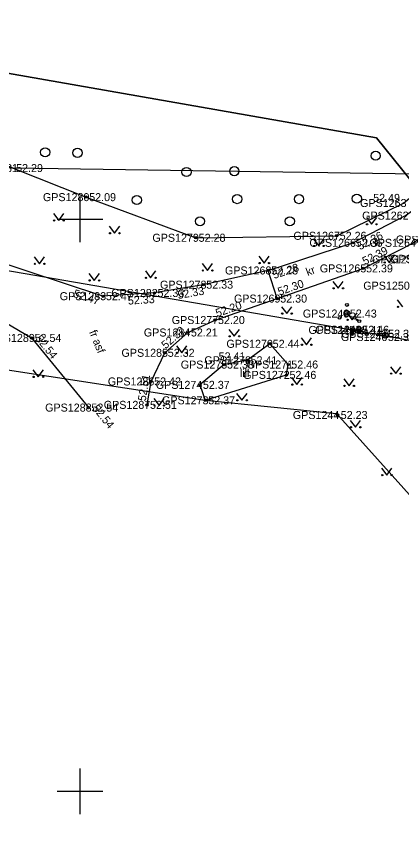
# Model space of a CAD drawing. Extents: x 551623 to 559850, y 6561220 to 6567135.
# Drawn here: x 555194.4 to 555228.1, y 6565096.7 to 6565167.7 of the extents above; entities that cross this region are included whole.
import ezdxf

# ---------------------------------------------------------------- set-up
doc = ezdxf.new("R2010")
doc.units = 0
for name, color, linetype in [('HALJASTUS', 7, 'Continuous'), ('KORGUS-EH2000', 7, 'Continuous'), ('KPOHULIIN', 7, 'Continuous'), ('MOOTKORG-EH2000', 7, 'Continuous'), ('MOOTMPUNKT', 7, 'Continuous'), ('MOOTNR', 7, 'Continuous'), ('MOOTPIIR', 7, 'Continuous'), ('PIIR', 7, 'Continuous'), ('POST', 7, 'Continuous'), ('PUU', 7, 'Continuous'), ('TEE', 7, 'Continuous'), ('VORK', 7, 'Continuous')]:
    doc.layers.add(name, color=color, linetype=linetype)

msp = doc.modelspace()

# ---------------------------------------------------------------- linework, layer by layer
at = {"layer": 'HALJASTUS'}
for p, q in [((555197.689, 6565150.508), (555198.153, 6565149.901)), ((555198.153, 6565149.901), (555198.598, 6565150.508)), ((555225.009, 6565150.165), (555225.472, 6565149.558)), ((555225.472, 6565149.558), (555225.918, 6565150.165)), ((555202.562, 6565149.385), (555203.025, 6565148.778)), ((555203.025, 6565148.778), (555203.471, 6565149.385)), ((555220.397, 6565148.274), (555220.861, 6565147.667)), ((555220.861, 6565147.667), (555221.306, 6565148.274)), ((555196, 6565146.709), (555196.464, 6565146.102)), ((555196.464, 6565146.102), (555196.909, 6565146.709)), ((555215.626, 6565146.78), (555216.089, 6565146.173)), ((555216.089, 6565146.173), (555216.535, 6565146.78)), ((555226.548, 6565146.826), (555227.012, 6565146.219)), ((555227.012, 6565146.219), (555227.457, 6565146.826)), ((555210.669, 6565146.129), (555211.133, 6565145.522)), ((555211.133, 6565145.522), (555211.578, 6565146.129)), ((555200.786, 6565145.261), (555201.25, 6565144.654)), ((555201.25, 6565144.654), (555201.695, 6565145.261)), ((555205.711, 6565145.488), (555206.174, 6565144.881)), ((555206.174, 6565144.881), (555206.62, 6565145.488)), ((555222.085, 6565144.574), (555222.548, 6565143.967)), ((555222.548, 6565143.967), (555222.994, 6565144.574)), ((555227.704, 6565142.95), (555228.168, 6565142.343)), ((555217.602, 6565142.361), (555218.065, 6565141.754)), ((555218.065, 6565141.754), (555218.511, 6565142.361)), ((555223.308, 6565141.818), (555223.771, 6565141.211)), ((555223.771, 6565141.211), (555224.217, 6565141.818)), ((555213.012, 6565140.378), (555213.475, 6565139.771)), ((555213.475, 6565139.771), (555213.921, 6565140.378)), ((555219.32, 6565139.641), (555219.783, 6565139.034)), ((555219.783, 6565139.034), (555220.229, 6565139.641)), ((555208.419, 6565138.924), (555208.883, 6565138.317)), ((555208.883, 6565138.317), (555209.328, 6565138.924)), ((555195.895, 6565136.829), (555196.358, 6565136.222)), ((555196.358, 6565136.222), (555196.804, 6565136.829)), ((555227.113, 6565137.114), (555227.577, 6565136.508)), ((555227.577, 6565136.508), (555228.022, 6565137.114)), ((555218.486, 6565136.16), (555218.949, 6565135.553)), ((555218.949, 6565135.553), (555219.395, 6565136.16)), ((555223.035, 6565136.044), (555223.499, 6565135.437)), ((555223.499, 6565135.437), (555223.944, 6565136.044)), ((555213.68, 6565134.781), (555214.143, 6565134.175)), ((555214.143, 6565134.175), (555214.589, 6565134.781)), ((555206.451, 6565134.328), (555206.914, 6565133.721)), ((555206.914, 6565133.721), (555207.36, 6565134.328)), ((555223.598, 6565132.426), (555224.062, 6565131.819)), ((555224.062, 6565131.819), (555224.507, 6565132.426)), ((555226.335, 6565128.241), (555226.798, 6565127.634)), ((555226.798, 6565127.634), (555227.244, 6565128.241))]:
    msp.add_line(p, q, dxfattribs=at)
for points in [[(555170.849, 6565163.433), (555170.802, 6565162.422), (555180.588, 6565157.338), (555194.166, 6565154.476), (555200.547, 6565151.934), (555210.105, 6565148.383), (555222.421, 6565148.556), (555228.239, 6565151.421), (555231.104, 6565153.786)], [(555216.57, 6565139.116), (555214.639, 6565137.676), (555212.583, 6565137.299), (555210.474, 6565135.526), (555210.946, 6565134.177), (555218.038, 6565136.397), (555218.195, 6565137.306), (555216.57, 6565139.116)]]:
    msp.add_lwpolyline(points, dxfattribs=at)
for centre, radius in [((555196.963, 6565155.852), 0.4), ((555199.786, 6565155.81), 0.4), ((555225.824, 6565155.557), 0.4), ((555209.308, 6565154.124), 0.4), ((555213.479, 6565154.208), 0.4), ((555213.732, 6565151.763), 0.4), ((555219.125, 6565151.763), 0.4), ((555224.181, 6565151.805), 0.4), ((555204.968, 6565151.678), 0.4), ((555210.488, 6565149.823), 0.4), ((555218.325, 6565149.823), 0.4), ((555197.752, 6565149.901), 0.055), ((555198.581, 6565149.901), 0.055), ((555225.071, 6565149.558), 0.055), ((555225.9, 6565149.558), 0.055), ((555202.624, 6565148.778), 0.055), ((555203.453, 6565148.778), 0.055), ((555220.46, 6565147.667), 0.055), ((555221.289, 6565147.667), 0.055), ((555196.063, 6565146.102), 0.055), ((555196.892, 6565146.102), 0.055), ((555215.688, 6565146.173), 0.055), ((555216.517, 6565146.173), 0.055), ((555226.611, 6565146.219), 0.055), ((555227.44, 6565146.219), 0.055), ((555210.732, 6565145.522), 0.055), ((555211.56, 6565145.522), 0.055), ((555200.848, 6565144.654), 0.055), ((555201.677, 6565144.654), 0.055), ((555205.773, 6565144.881), 0.055), ((555206.602, 6565144.881), 0.055), ((555222.147, 6565143.967), 0.055), ((555222.976, 6565143.967), 0.055), ((555227.767, 6565142.343), 0.055), ((555217.664, 6565141.754), 0.055), ((555218.493, 6565141.754), 0.055), ((555223.37, 6565141.211), 0.055), ((555224.199, 6565141.211), 0.055), ((555213.074, 6565139.771), 0.055), ((555213.903, 6565139.771), 0.055), ((555219.382, 6565139.034), 0.055), ((555220.211, 6565139.034), 0.055), ((555208.482, 6565138.317), 0.055), ((555209.311, 6565138.317), 0.055), ((555227.175, 6565136.508), 0.055), ((555228.004, 6565136.508), 0.055), ((555195.957, 6565136.222), 0.055), ((555196.786, 6565136.222), 0.055), ((555218.548, 6565135.553), 0.055), ((555219.377, 6565135.553), 0.055), ((555223.098, 6565135.437), 0.055), ((555223.927, 6565135.437), 0.055), ((555206.513, 6565133.721), 0.055), ((555207.342, 6565133.721), 0.055), ((555213.742, 6565134.175), 0.055), ((555214.571, 6565134.175), 0.055), ((555223.661, 6565131.819), 0.055), ((555224.49, 6565131.819), 0.055), ((555226.397, 6565127.634), 0.055), ((555227.226, 6565127.634), 0.055)]:
    msp.add_circle(centre, radius, dxfattribs=at)
at = {"layer": 'KORGUS-EH2000'}
for centre in [(555200.547, 6565151.934), (555222.421, 6565148.556), (555210.105, 6565148.383), (555223.819, 6565147.942), (555224.725, 6565145.706), (555216.442, 6565145.526), (555210.771, 6565144.283), (555206.511, 6565143.557), (555202.006, 6565143.277), (555217.229, 6565143.067), (555223.313, 6565141.76), (555211.794, 6565141.192), (555195.778, 6565139.63), (555207.407, 6565138.329), (555214.639, 6565137.676), (555218.038, 6565136.397), (555205.86, 6565133.779), (555210.946, 6565134.177), (555200.739, 6565133.541), (555222.511, 6565132.893)]:
    msp.add_circle(centre, 0.1, dxfattribs=at)
at = {"layer": 'KPOHULIIN'}
msp.add_lwpolyline([(555148.701, 6565153.258), (555226.644, 6565139.855), (555319.309, 6565121.586)], dxfattribs=at)
at = {"layer": 'MOOTMPUNKT'}
for centre in [(555200.547, 6565151.934), (555222.421, 6565148.556), (555210.105, 6565148.383), (555223.819, 6565147.942), (555224.725, 6565145.706), (555216.442, 6565145.526), (555210.771, 6565144.283), (555206.511, 6565143.557), (555202.006, 6565143.277), (555217.229, 6565143.067), (555223.313, 6565141.76), (555211.794, 6565141.192), (555209.429, 6565140.104), (555223.805, 6565140.327), (555224.394, 6565140.342), (555226.654, 6565139.998), (555195.778, 6565139.63), (555226.633, 6565139.711), (555216.57, 6565139.116), (555207.407, 6565138.329), (555212.583, 6565137.299), (555214.639, 6565137.676), (555218.195, 6565137.306), (555218.038, 6565136.397), (555206.217, 6565135.824), (555210.474, 6565135.526), (555205.86, 6565133.779), (555210.946, 6565134.177), (555200.739, 6565133.541), (555222.511, 6565132.893)]:
    msp.add_circle(centre, 0.1, dxfattribs=at)
at = {"layer": 'MOOTPIIR'}
for points in [[(555288.412, 6565133.905), (555268.035, 6565138.732), (555253.525, 6565143.622), (555235.12, 6565151.155), (555234.467, 6565152.147), (555233.413, 6565153.879), (555194.166, 6565154.476), (555170.849, 6565163.433), (555168.744, 6565163.563), (555174.483, 6565185.521), (555180.709, 6565208.971), (555185.087, 6565226.838), (555186.799, 6565233.51), (555187.911, 6565235.651), (555189.563, 6565248.443)], [(555147.465, 6565082.979), (555153.125, 6565104.459), (555157.981, 6565122.311), (555163.2, 6565141.618), (555175.303, 6565138.726), (555190.232, 6565137.368), (555210.946, 6565134.177), (555222.4, 6565133.017), (555236.459, 6565117.362), (555247.686, 6565098.015), (555255.514, 6565098.946), (555277.06, 6565106.584), (555291.997, 6565107.634)]]:
    msp.add_lwpolyline(points, dxfattribs=at)
at = {"layer": 'PIIR'}
msp.add_lwpolyline([(555288.85, 6565092.31), (555275.41, 6565088.83), (555273.15, 6565087.34), (555239.11, 6565139), (555231.12, 6565150.64), (555225.89, 6565157.13), (555173.21, 6565166.35), (555173.84, 6565168.77), (555191.64, 6565237.48), (555195.28, 6565271.63), (555195.08, 6565294.61), (555205.15, 6565297.11), (555275.38, 6565300.17), (555292.52, 6565297.57)], dxfattribs=at)
msp.add_lwpolyline([(555172.58, 6565163.93), (555173.21, 6565166.35), (555225.89, 6565157.13), (555231.12, 6565150.64), (555239.11, 6565139), (555273.15, 6565087.34), (555275.41, 6565088.83), (555288.85, 6565092.31), (555289.83, 6565088.53), (555295.15, 6565083.63), (555324.46, 6565074.96), (555339.51, 6565058.58), (555337.29, 6565046.66), (555323.9, 6565035.68), (555298.08, 6565033.06), (555286.82, 6565022.41), (555284.62, 6565010.72), (555273.43, 6565013.07), (555140.74, 6565041.04)], close=True, dxfattribs=at)
at = {"layer": 'POST'}
msp.add_lwpolyline([(555223.805, 6565140.327), (555226.644, 6565139.855)], dxfattribs=at)
for centre, radius in [((555223.805, 6565140.327), 0.2), ((555226.644, 6565139.855), 0.25), ((555226.644, 6565139.855), 0.0234)]:
    msp.add_circle(centre, radius, dxfattribs=at)
at = {"layer": 'PUU'}
for centre, radius in [((555223.313, 6565142.51), 0.125), ((555222.663, 6565141.385), 0.125), ((555223.313, 6565141.76), 0.25), ((555223.963, 6565141.385), 0.125), ((555224.394, 6565141.092), 0.125), ((555223.744, 6565139.967), 0.125), ((555224.394, 6565140.342), 0.25), ((555225.044, 6565139.967), 0.125)]:
    msp.add_circle(centre, radius, dxfattribs=at)
at = {"layer": 'TEE'}
for points in [[(555205.86, 6565133.779), (555206.217, 6565135.824), (555207.407, 6565138.329), (555209.429, 6565140.104), (555211.794, 6565141.192), (555217.229, 6565143.067), (555216.442, 6565145.526), (555210.771, 6565144.283), (555206.511, 6565143.557), (555202.006, 6565143.277), (555191.831, 6565146.626), (555179.65, 6565150.043), (555174.155, 6565151.803), (555172.54, 6565153.141), (555170.207, 6565157.377), (555168.463, 6565160.669), (555168.3, 6565162.209)], [(555216.442, 6565145.526), (555223.819, 6565147.942), (555228.422, 6565150.319), (555233.413, 6565153.879)], [(555217.229, 6565143.067), (555224.725, 6565145.706), (555229.126, 6565147.942), (555234.467, 6565152.147)], [(555163.2, 6565141.618), (555168.594, 6565144.246), (555172.571, 6565146.598), (555178.227, 6565145.611), (555191.847, 6565141.953), (555195.778, 6565139.63), (555200.739, 6565133.541)]]:
    msp.add_lwpolyline(points, dxfattribs=at)
at = {"layer": 'VORK'}
for p, q in [((555200, 6565152), (555200, 6565148)), ((555198, 6565150), (555202, 6565150)), ((555200, 6565102), (555200, 6565098)), ((555198, 6565100), (555202, 6565100))]:
    msp.add_line(p, q, dxfattribs=at)

# ---------------------------------------------------------------- texts
at = {"layer": 'HALJASTUS'}
msp.add_text('lill', height=0.7, dxfattribs=at).set_placement((555213.967, 6565136.212))
at = {"layer": 'KORGUS-EH2000'}
for s, p in [(' 52.29', (555194.166, 6565154.126)), (' 52.09', (555200.547, 6565151.584)), (' 52.49', (555225.346, 6565151.518)), (' 52.28', (555210.105, 6565148.033)), (' 52.26', (555222.421, 6565148.206)), (' 52.43', (555223.313, 6565141.41)), (' 52.41', (555211.85, 6565137.669)), (' 52.46', (555218.038, 6565136.047)), (' 52.37', (555210.946, 6565133.827)), (' 52.23', (555222.511, 6565132.543))]:
    msp.add_text(s, height=0.7, dxfattribs=at).set_placement(p)
for s, rotation, p in [(' 52.36', 27.30461, (555224.221, 6565147.165)), (' 52.39', 26.93515, (555224.645, 6565145.862)), (' 52.28', 18.13878, (555216.714, 6565144.694)), (' 52.30', 19.39732, (555217.17, 6565143.232)), (' 52.47', 341.7841, (555199.111, 6565143.312)), (' 52.33', 9.67505, (555208.326, 6565142.984)), (' 52.33', 3.55163, (555203.944, 6565142.52)), (' 52.20', 19.02778, (555211.737, 6565141.358)), (' 52.32', 41.26165, (555207.291, 6565138.461)), (' 52.54', 309.17649, (555195.913, 6565139.74)), (' 52.51', 80.08857, (555205.687, 6565133.809)), (' 52.54', 309.17649, (555200.875, 6565133.652))]:
    msp.add_text(s, height=0.7, rotation=rotation, dxfattribs=at).set_placement(p)
at = {"layer": 'MOOTKORG-EH2000'}
for s, p in [(' 52.29', (555194.166, 6565154.126)), (' 52.09', (555200.547, 6565151.584)), (' 52.28', (555210.105, 6565148.033)), (' 52.26', (555222.421, 6565148.206)), (' 52.36', (555223.819, 6565147.593)), (' 52.28', (555216.442, 6565145.176)), (' 52.39', (555224.725, 6565145.356)), (' 52.33', (555210.771, 6565143.933)), (' 52.47', (555202.006, 6565142.927)), (' 52.33', (555206.511, 6565143.207)), (' 52.30', (555217.229, 6565142.717)), (' 52.20', (555211.794, 6565140.843)), (' 52.43', (555223.313, 6565141.41)), (' 52.21', (555209.429, 6565139.754)), (' 52.41', (555223.805, 6565139.977)), (' 52.46', (555224.394, 6565139.992)), (' 52.36', (555226.633, 6565139.361)), (' 52.35', (555226.654, 6565139.648)), (' 52.54', (555195.778, 6565139.28)), (' 52.44', (555216.57, 6565138.766)), (' 52.32', (555207.407, 6565137.979)), (' 52.41', (555214.639, 6565137.326)), (' 52.38', (555212.583, 6565136.949)), (' 52.46', (555218.195, 6565136.956)), (' 52.46', (555218.038, 6565136.047)), (' 52.42', (555206.217, 6565135.474)), (' 52.37', (555210.474, 6565135.177)), (' 52.37', (555210.946, 6565133.827)), (' 52.54', (555200.739, 6565133.191)), (' 52.51', (555205.86, 6565133.429)), (' 52.23', (555222.511, 6565132.543))]:
    msp.add_text(s, height=0.7, dxfattribs=at).set_placement(p)
at = {"layer": 'MOOTNR'}
for s, p in [('GPS1281 ', (555190.526, 6565154.126)), ('GPS1280 ', (555196.767, 6565151.584)), ('GPS1263 ', (555224.459, 6565151.071)), ('GPS1262 ', (555224.642, 6565149.969)), ('GPS1279 ', (555206.325, 6565148.033)), ('GPS1267 ', (555218.642, 6565148.206)), ('GPS1253 ', (555227.587, 6565147.88)), ('GPS1266 ', (555220.039, 6565147.593)), ('GPS1264 ', (555225.276, 6565147.592)), ('GPS1251 ', (555225.511, 6565146.14)), ('GPS1252 ', (555227.07, 6565146.193)), ('GPS1268 ', (555212.662, 6565145.176)), ('GPS1265 ', (555220.945, 6565145.356)), ('GPS1278 ', (555206.991, 6565143.933)), ('GPS1250 ', (555224.741, 6565143.846)), ('GPS1283 ', (555198.226, 6565142.927)), ('GPS1282 ', (555202.731, 6565143.207)), ('GPS1269 ', (555213.449, 6565142.717)), ('GPS1277 ', (555208.014, 6565140.843)), ('GPS1249 ', (555219.463, 6565141.41)), ('GPS1284 ', (555205.58, 6565139.754)), ('GPS1245 ', (555219.955, 6565139.977)), ('GPS1248 ', (555220.545, 6565139.992)), ('GPS1246 ', (555222.784, 6565139.361)), ('GPS1247 ', (555222.804, 6565139.648)), ('GPS1289 ', (555191.998, 6565139.28)), ('GPS1270 ', (555212.79, 6565138.766)), ('GPS1285 ', (555203.627, 6565137.979)), ('GPS1276 ', (555210.859, 6565137.326)), ('GPS1275 ', (555208.804, 6565136.949)), ('GPS1271 ', (555214.556, 6565136.956)), ('GPS1272 ', (555214.258, 6565136.047)), ('GPS1286 ', (555202.437, 6565135.474)), ('GPS1274 ', (555206.624, 6565135.177)), ('GPS1273 ', (555207.167, 6565133.827)), ('GPS1288 ', (555196.96, 6565133.191)), ('GPS1287 ', (555202.08, 6565133.429)), ('GPS1244 ', (555218.591, 6565132.543))]:
    msp.add_text(s, height=0.7, dxfattribs=at).set_placement(p)
at = {"layer": 'TEE'}
for s, rotation, p in [('kr', 20.47111, (555219.887, 6565145.031)), ('fr asf', 292.26465, (555200.789, 6565140.147))]:
    msp.add_text(s, height=0.7, rotation=rotation, dxfattribs=at).set_placement(p)

doc.saveas('drawing.dxf')
